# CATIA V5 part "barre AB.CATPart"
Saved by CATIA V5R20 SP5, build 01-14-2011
Part number: barre AB
Bounding box of the stored display mesh (mm): x 0 to 10, y -9.902 to 111.459, z -9.902 to 182.199
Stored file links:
  F:\projet\yyang_IAO\barre AB.CATPart
  F:\projet\yyang_IAO\iao.CATProduct
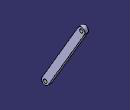
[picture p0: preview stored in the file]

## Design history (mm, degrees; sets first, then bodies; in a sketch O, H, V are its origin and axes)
External parameters (linked from other documents)
  `External.rayon de liaison` = 5 mm
  External.epaisseur = 10 mm
  External.Largeur = 20 mm
Set1
  Plane1: linked copy from another document
  Point1: linked copy from another document
  Point2: linked copy from another document
  Line1: linked copy from another document
Body1 (main body)
  Sketch1 on Plane1, origin (0, 0, 0), H (0, 1, 0), V (0, 0, 1)
    circle A1 centre (0, 0) radius 5
    point P1 (0, 0)
    reference projected point E1 (0, 0) from Point1
    reference projected point E2 (0, 0) from Point1
    circle A2 centre (101.5571, 172.2967) radius 5
    point P2 (101.5571, 172.2967)
    reference projected point E3 (101.5571, 172.2967) from Point2
    reference projected point E4 (101.5571, 172.2967) from Point2
    construction line L1 (0, 0) -> (101.5571, 172.2967)
    point P3 (0, 0)
    point P4 (101.5571, 172.2967)
    line L2 (-8.6148, 5.0779) -> (92.9422, 177.3746)
    line L3 (110.1719, 167.2189) -> (8.6148, -5.0779)
    arc A3 centre (101.5571, 172.2967) radius 10 from (92.9422, 177.3746) to (110.1719, 167.2189) cw
    arc A4 centre (0, 0) radius 10 from (8.6148, -5.0779) to (-8.6148, 5.0779) cw
    reference projected point E5 (0, 0) from Point1
    reference projected point E6 (101.5571, 172.2967) from Point2
    distance A1 E2 = 5 {= `External.rayon de liaison`}
    distance E4 A2 = 5 {= `External.rayon de liaison`}
    distance L1 L2 = 10 {= External.Largeur/2}
    coincidence: P1 E1, P2 E3, P3 E5, P4 E6
    tangency: A3 L2, A4 L2, A3 L3, A4 L3
  Pad1: profile Sketch1, direction (1, 0, 0), length 10 {= External.epaisseur}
